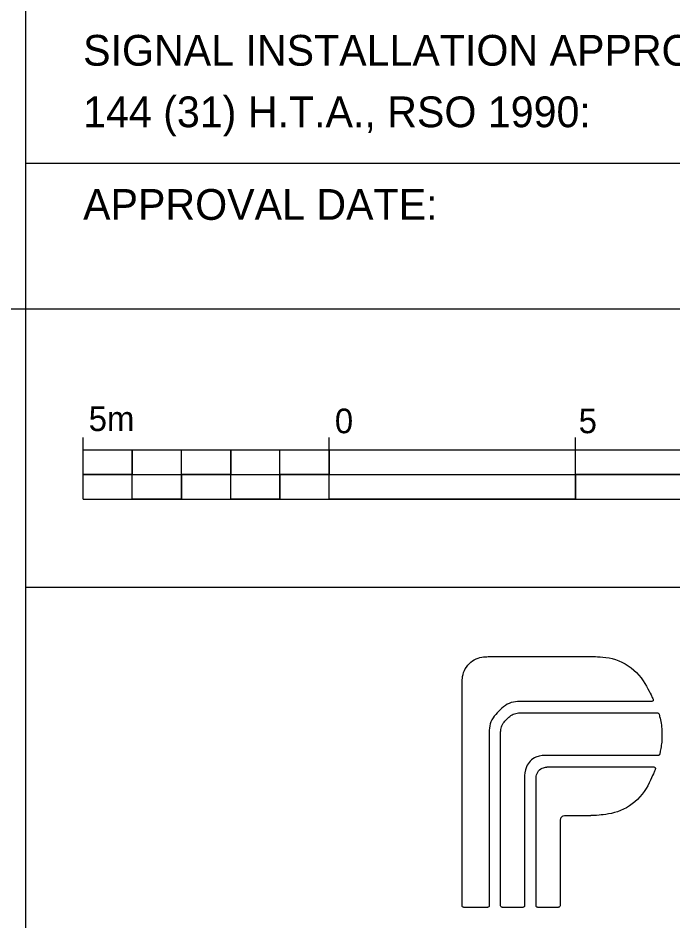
# Model space of a CAD drawing. Extents: x 612883 to 613093, y 4825734 to 4825879.
# Drawn here: x 613058.24 to 613071.55, y 4825752.15 to 4825770.49 of the extents above; entities that cross this region are included whole.
import ezdxf

# ---------------------------------------------------------------- set-up
doc = ezdxf.new("R2010")
doc.units = 0
for name, color, linetype in [('G-ANNO-BAR', 7, 'Continuous'), ('G-ANNO-TEXT', 7, 'Continuous'), ('G-TTLB-LOGO', 7, 'Continuous'), ('G-TTLB-OTLN', 7, 'Continuous')]:
    doc.layers.add(name, color=color, linetype=linetype)

msp = doc.modelspace()

# ---------------------------------------------------------------- linework, layer by layer
at = {"layer": 'G-ANNO-BAR'}
for p, q in [((613059.564, 4825760.723), (613059.564, 4825761.973)), ((613064.564, 4825760.723), (613064.564, 4825761.973)), ((613069.564, 4825760.723), (613069.564, 4825761.973)), ((613059.564, 4825761.723), (613079.564, 4825761.723)), ((613060.564, 4825760.723), (613060.564, 4825761.723)), ((613061.564, 4825760.723), (613061.564, 4825761.723)), ((613062.564, 4825760.723), (613062.564, 4825761.723)), ((613063.564, 4825760.723), (613063.564, 4825761.723)), ((613059.564, 4825761.223), (613079.564, 4825761.223)), ((613059.564, 4825760.723), (613079.564, 4825760.723))]:
    msp.add_line(p, q, dxfattribs=at)
for points in [[(613059.564, 4825761.723), (613060.564, 4825761.723), (613060.564, 4825761.223), (613059.564, 4825761.223)], [(613061.564, 4825761.723), (613062.564, 4825761.723), (613062.564, 4825761.223), (613061.564, 4825761.223)], [(613063.564, 4825761.723), (613064.564, 4825761.723), (613064.564, 4825761.223), (613063.564, 4825761.223)], [(613069.564, 4825761.723), (613074.564, 4825761.723), (613074.564, 4825761.223), (613069.564, 4825761.223)], [(613060.564, 4825761.223), (613061.564, 4825761.223), (613061.564, 4825760.723), (613060.564, 4825760.723)], [(613062.564, 4825761.223), (613063.564, 4825761.223), (613063.564, 4825760.723), (613062.564, 4825760.723)], [(613064.564, 4825761.223), (613069.564, 4825761.223), (613069.564, 4825760.723), (613064.564, 4825760.723)]]:
    msp.add_lwpolyline(points, close=True, dxfattribs=at)
at = {"layer": 'G-TTLB-LOGO'}
for points in [[(613071.116, 4825756.611), (613071.129, 4825756.611), (613071.145, 4825756.624), (613071.145, 4825756.642), (613071.145, 4825756.649), (613071.142, 4825756.658), (613071.141, 4825756.659), (613070.899, 4825757.171), (613070.384, 4825757.522), (613069.843, 4825757.522), (613069.843, 4825757.522), (613067.874, 4825757.522), (613067.874, 4825757.522), (613067.537, 4825757.522), (613067.263, 4825757.248), (613067.263, 4825756.911), (613067.263, 4825756.911), (613067.263, 4825752.471), (613067.263, 4825752.471), (613067.263, 4825752.448), (613067.282, 4825752.43), (613067.305, 4825752.43), (613067.305, 4825752.43), (613067.773, 4825752.43), (613067.773, 4825752.43), (613067.796, 4825752.43), (613067.814, 4825752.448), (613067.814, 4825752.471), (613067.814, 4825752.471), (613067.815, 4825755.938), (613067.815, 4825755.938), (613067.813, 4825756.115), (613067.881, 4825756.284), (613068.007, 4825756.411), (613068.134, 4825756.54), (613068.303, 4825756.611), (613068.484, 4825756.611), (613068.484, 4825756.611), (613071.116, 4825756.611), (613071.116, 4825756.611)], [(613071.116, 4825756.611), (613071.129, 4825756.611), (613071.145, 4825756.624), (613071.145, 4825756.642), (613071.145, 4825756.649), (613071.142, 4825756.658), (613071.141, 4825756.659), (613070.899, 4825757.171), (613070.384, 4825757.522), (613069.843, 4825757.522), (613069.843, 4825757.522), (613067.874, 4825757.522), (613067.874, 4825757.522), (613067.537, 4825757.522), (613067.263, 4825757.248), (613067.263, 4825756.911), (613067.263, 4825756.911), (613067.263, 4825752.471), (613067.263, 4825752.471), (613067.263, 4825752.448), (613067.282, 4825752.43), (613067.305, 4825752.43), (613067.305, 4825752.43), (613067.773, 4825752.43), (613067.773, 4825752.43), (613067.796, 4825752.43), (613067.814, 4825752.448), (613067.814, 4825752.471), (613067.814, 4825752.471), (613067.815, 4825755.938), (613067.815, 4825755.938), (613067.813, 4825756.115), (613067.881, 4825756.284), (613068.007, 4825756.411), (613068.134, 4825756.54), (613068.303, 4825756.611), (613068.484, 4825756.611), (613068.484, 4825756.611), (613071.116, 4825756.611), (613071.116, 4825756.611)], [(613071.254, 4825756.37), (613071.248, 4825756.376), (613071.24, 4825756.381), (613071.23, 4825756.381), (613071.23, 4825756.381), (613068.468, 4825756.381), (613068.468, 4825756.381), (613068.355, 4825756.377), (613068.249, 4825756.331), (613068.17, 4825756.251), (613068.092, 4825756.172), (613068.048, 4825756.069), (613068.045, 4825755.959), (613068.045, 4825755.959), (613068.045, 4825752.471), (613068.045, 4825752.471), (613068.045, 4825752.448), (613068.064, 4825752.43), (613068.087, 4825752.43), (613068.087, 4825752.43), (613068.491, 4825752.43), (613068.491, 4825752.43), (613068.514, 4825752.43), (613068.532, 4825752.448), (613068.532, 4825752.471), (613068.532, 4825752.471), (613068.532, 4825755.022), (613068.532, 4825755.022), (613068.532, 4825755.294), (613068.754, 4825755.516), (613069.027, 4825755.516), (613069.027, 4825755.516), (613071.246, 4825755.516), (613071.246, 4825755.516), (613071.26, 4825755.517), (613071.272, 4825755.527), (613071.275, 4825755.539), (613071.276, 4825755.54), (613071.276, 4825755.54), (613071.276, 4825755.541), (613071.299, 4825755.656), (613071.32, 4825755.788), (613071.32, 4825755.906), (613071.32, 4825756.057), (613071.301, 4825756.205), (613071.264, 4825756.349), (613071.261, 4825756.362), (613071.257, 4825756.366), (613071.254, 4825756.37)], [(613071.254, 4825756.37), (613071.248, 4825756.376), (613071.24, 4825756.381), (613071.23, 4825756.381), (613071.23, 4825756.381), (613068.468, 4825756.381), (613068.468, 4825756.381), (613068.355, 4825756.377), (613068.249, 4825756.331), (613068.17, 4825756.251), (613068.092, 4825756.172), (613068.048, 4825756.069), (613068.045, 4825755.959), (613068.045, 4825755.959), (613068.045, 4825752.471), (613068.045, 4825752.471), (613068.045, 4825752.448), (613068.064, 4825752.43), (613068.087, 4825752.43), (613068.087, 4825752.43), (613068.491, 4825752.43), (613068.491, 4825752.43), (613068.514, 4825752.43), (613068.532, 4825752.448), (613068.532, 4825752.471), (613068.532, 4825752.471), (613068.532, 4825755.022), (613068.532, 4825755.022), (613068.532, 4825755.294), (613068.754, 4825755.516), (613069.027, 4825755.516), (613069.027, 4825755.516), (613071.246, 4825755.516), (613071.246, 4825755.516), (613071.26, 4825755.517), (613071.272, 4825755.527), (613071.275, 4825755.539), (613071.276, 4825755.54), (613071.276, 4825755.54), (613071.276, 4825755.541), (613071.299, 4825755.656), (613071.32, 4825755.788), (613071.32, 4825755.906), (613071.32, 4825756.057), (613071.301, 4825756.205), (613071.264, 4825756.349), (613071.261, 4825756.362), (613071.257, 4825756.366), (613071.254, 4825756.37)], [(613071.155, 4825755.282), (613071.155, 4825755.282), (613069.025, 4825755.282), (613069.013, 4825755.282), (613069.002, 4825755.282), (613068.979, 4825755.28), (613068.971, 4825755.278), (613068.858, 4825755.254), (613068.771, 4825755.155), (613068.765, 4825755.036), (613068.765, 4825755.036), (613068.765, 4825752.471), (613068.765, 4825752.471), (613068.765, 4825752.448), (613068.783, 4825752.43), (613068.806, 4825752.43), (613068.806, 4825752.43), (613069.21, 4825752.43), (613069.21, 4825752.43), (613069.233, 4825752.43), (613069.252, 4825752.448), (613069.252, 4825752.471), (613069.252, 4825752.471), (613069.252, 4825754.164), (613069.252, 4825754.164), (613069.252, 4825754.235), (613069.309, 4825754.292), (613069.38, 4825754.292), (613069.38, 4825754.292), (613069.877, 4825754.292), (613069.877, 4825754.292), (613069.877, 4825754.292), (613069.946, 4825754.294), (613069.964, 4825754.296), (613070.491, 4825754.343), (613070.961, 4825754.699), (613071.184, 4825755.229), (613071.189, 4825755.239), (613071.189, 4825755.255), (613071.184, 4825755.264), (613071.178, 4825755.277), (613071.168, 4825755.282), (613071.155, 4825755.282)], [(613071.155, 4825755.282), (613071.155, 4825755.282), (613069.025, 4825755.282), (613069.013, 4825755.282), (613069.002, 4825755.282), (613068.979, 4825755.28), (613068.971, 4825755.278), (613068.858, 4825755.254), (613068.771, 4825755.155), (613068.765, 4825755.036), (613068.765, 4825755.036), (613068.765, 4825752.471), (613068.765, 4825752.471), (613068.765, 4825752.448), (613068.783, 4825752.43), (613068.806, 4825752.43), (613068.806, 4825752.43), (613069.21, 4825752.43), (613069.21, 4825752.43), (613069.233, 4825752.43), (613069.252, 4825752.448), (613069.252, 4825752.471), (613069.252, 4825752.471), (613069.252, 4825754.164), (613069.252, 4825754.164), (613069.252, 4825754.235), (613069.309, 4825754.292), (613069.38, 4825754.292), (613069.38, 4825754.292), (613069.877, 4825754.292), (613069.877, 4825754.292), (613069.877, 4825754.292), (613069.946, 4825754.294), (613069.964, 4825754.296), (613070.491, 4825754.343), (613070.961, 4825754.699), (613071.184, 4825755.229), (613071.189, 4825755.239), (613071.189, 4825755.255), (613071.184, 4825755.264), (613071.178, 4825755.277), (613071.168, 4825755.282), (613071.155, 4825755.282)]]:
    msp.add_open_spline(points, degree=3, dxfattribs=at)
at = {"layer": 'G-TTLB-OTLN'}
for p, q in [((613058.399, 4825734.927), (613058.399, 4825869.211)), ((613090.1, 4825767.538), (613058.399, 4825767.538)), ((612893.054, 4825764.585), (613090.1, 4825764.584)), ((613090.1, 4825758.926), (613058.399, 4825758.926))]:
    msp.add_line(p, q, dxfattribs=at)

# ---------------------------------------------------------------- texts
at = {"layer": 'G-ANNO-BAR'}
msp.add_text('5m', height=0.5, dxfattribs=at).set_placement((613059.678, 4825762.105))
for s, p in [('0', (613064.678, 4825762.06)), ('5', (613069.63, 4825762.061))]:
    msp.add_text(s, height=0.5, rotation=360, dxfattribs=at).set_placement(p)
at = {"layer": 'G-ANNO-TEXT'}
for s, p in [('SIGNAL INSTALLATION APPROVED AS PER SECTION', (613059.565, 4825769.526)), ('144 (31) H.T.A., RSO 1990:', (613059.565, 4825768.276)), ('APPROVAL DATE:', (613059.565, 4825766.395))]:
    msp.add_text(s, height=0.625, dxfattribs=at).set_placement(p)

doc.saveas('drawing.dxf')
